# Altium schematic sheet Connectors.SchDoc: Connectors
size A3; Date: Not used; ApprovedBy: Not used; CheckedBy: Not used; Author: Not used; CompanyName: STMicroelectronics; DrawnBy: Not used; Engineer: Not used; Organization: Not used; Address1: Not used; Address2: Not used; Address3: Not used; Address4: Not used; DocumentNumber: 5; Revision: Not used; SheetNumber: 5; SheetTotal: 9
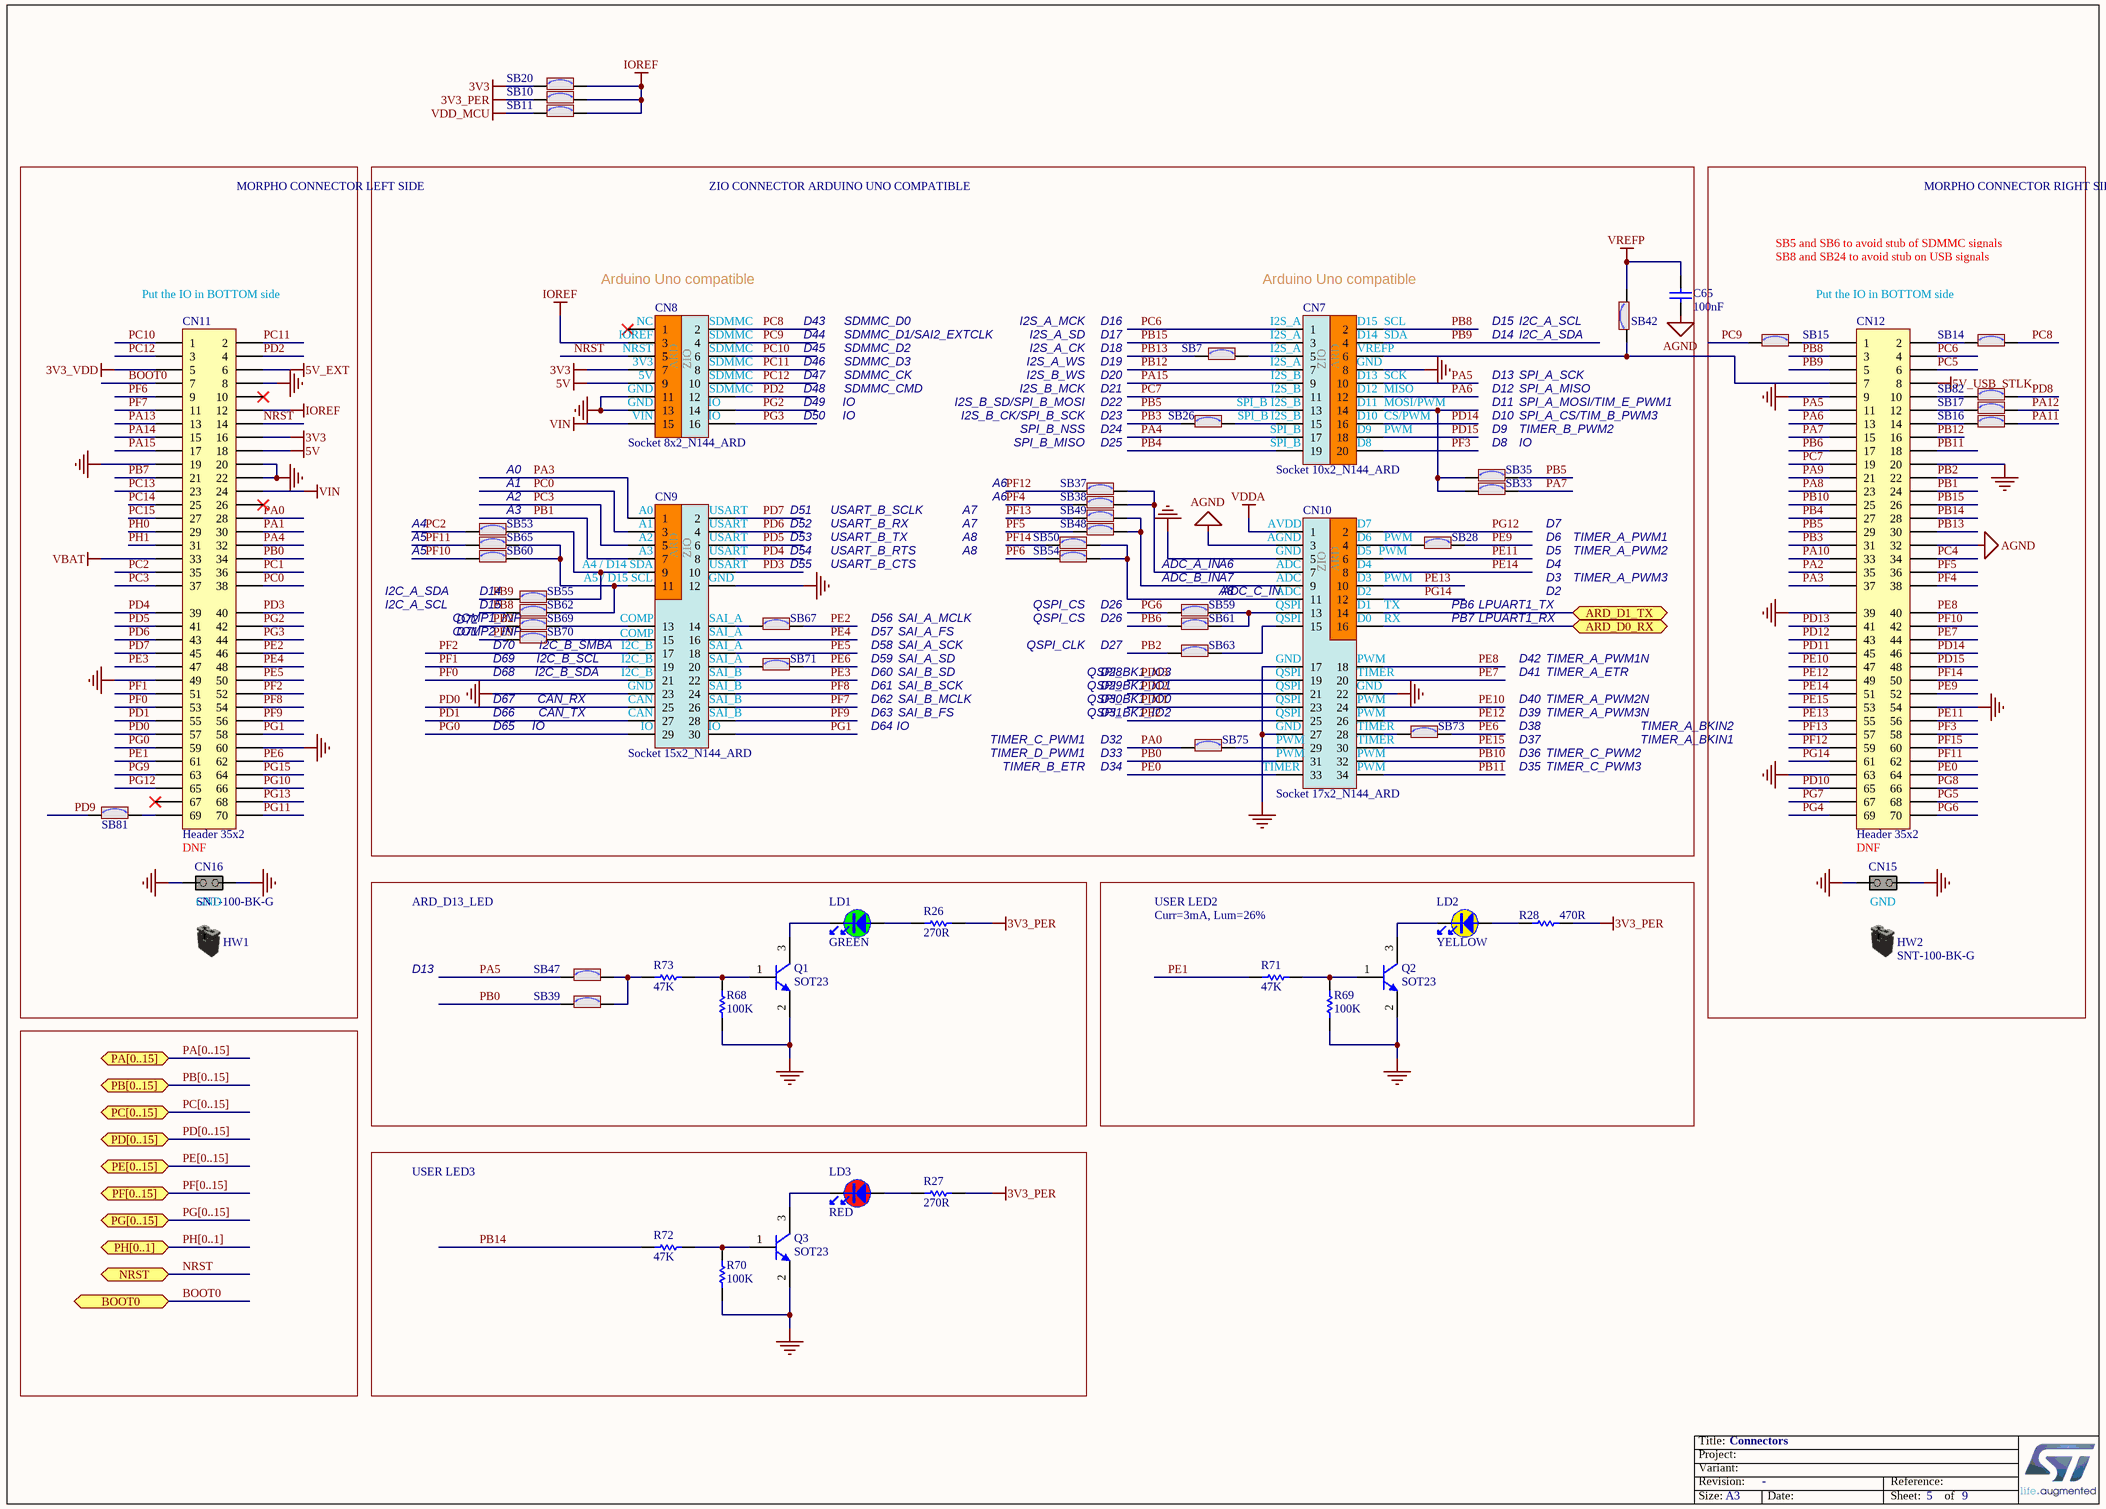
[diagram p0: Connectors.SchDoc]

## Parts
C65  value 100nF  [C0603]  (hidden comment: Capacitor)
CN7  Socket 10x2_N144_ARD  [CON_SAMTEC_SSW-110-23-X-D_N144_ARD]
CN8  Socket 8x2_N144_ARD  [CON_SAMTEC_SSW-108-23-X-D_N144_ARD]
CN9  Socket 15x2_N144_ARD  [CON_SAMTEC_SSW-115-23-X-D_N144_ARD]
CN10  Socket 17x2_N144_ARD  [CON_SAMTEC_SSW-117-23-X-D_N144_ARD]
CN11  Header 35x2  [CON_SAMTEC_TSW-135-07-X-D]
CN12  Header 35x2  [CON_SAMTEC_TSW-135-07-X-D]
CN15  Jumper_Header 2x1  [CON_SAMTEC_TSW-102-09-X-S]  (value not drawn)
CN16  Jumper_Header 2x1  [CON_SAMTEC_TSW-102-09-X-S]  (value not drawn)
HW1  value SNT-100-BK-G  (hidden comment: Shunt Black 2.54mm)  (mechanical)
HW2  value SNT-100-BK-G  (hidden comment: Shunt Black 2.54mm)  (mechanical)
LD1  value GREEN  [LED_0603_OSRAM_LG-Q396-PS-35_GREEN_1A2K_H0P4]  (hidden comment: LED_green)
LD2  value YELLOW  [LED_0603_OSRAM_LY-Q396-P1Q2-36_YELLOW_1A2K_H0P4]  (hidden comment: LED_yellow)
LD3  value RED  [LED_0603_OSRAM_LS-Q976-NR-1_RED_1A2K_H0P8]  (hidden comment: LED_red)
Q1  value SOT23  [NPN_SOT23]  (hidden comment: 9013-SOT23)
Q2  value SOT23  [NPN_SOT23]  (hidden comment: 9013-SOT23)
Q3  value SOT23  [NPN_SOT23]  (hidden comment: 9013-SOT23)
R26  value 270R  [R0402]  (hidden comment: Resistor)
R27  value 270R  [R0402]  (hidden comment: Resistor)
R28  value 470R  [R0402]  (hidden comment: Resistor)
R68  value 100K  [R0603]  (hidden comment: Resistor)
R69  value 100K  [R0603]  (hidden comment: Resistor)
R70  value 100K  [R0603]  (hidden comment: Resistor)
R71  value 47K  [R0603]  (hidden comment: Resistor)
R72  value 47K  [R0603]  (hidden comment: Resistor)
R73  value 47K  [R0603]  (hidden comment: Resistor)
SB7  SB_ON  [SOLDER-BRIDGE_R0603-0R]  (value not drawn)
SB10  SB_ON  [SOLDER-BRIDGE_R0603-0R]  (value not drawn)
SB11  SB_ON  [SOLDER-BRIDGE_R0603-0R]  (value not drawn)
SB14  SB_ON  [SOLDER-BRIDGE_R0603-0R]  (value not drawn)
SB15  SB_ON  [SOLDER-BRIDGE_R0603-0R]  (value not drawn)
SB16  SB_ON  [SOLDER-BRIDGE_R0603-0R]  (value not drawn)
SB17  SB_ON  [SOLDER-BRIDGE_R0603-0R]  (value not drawn)
SB20  SB_ON  [SOLDER-BRIDGE_R0603-0R]  (value not drawn)
SB26  SB_ON  [SOLDER-BRIDGE_R0603-0R]  (value not drawn)
SB28  SB_ON  [SOLDER-BRIDGE_R0402-0R]  (value not drawn)
SB33  SB_ON  [SOLDER-BRIDGE_R0603-0R]  (value not drawn)
SB35  SB_ON  [SOLDER-BRIDGE_R0603-0R]  (value not drawn)
SB37  SB_ON  [SOLDER-BRIDGE_R0402-0R]  (value not drawn)
SB38  SB_ON  [SOLDER-BRIDGE_R0402-0R]  (value not drawn)
SB39  SB_ON  [SOLDER-BRIDGE_R0603-0R]  (value not drawn)
SB42  SB_ON  [SOLDER-BRIDGE_R0603-0R]  (value not drawn)
SB47  SB_ON  [SOLDER-BRIDGE_R0603-0R]  (value not drawn)
SB48  SB_ON  [SOLDER-BRIDGE_R0402-0R]  (value not drawn)
SB49  SB_ON  [SOLDER-BRIDGE_R0402-0R]  (value not drawn)
SB50  SB_ON  [SOLDER-BRIDGE_R0402-0R]  (value not drawn)
SB53  SB_ON  [SOLDER-BRIDGE_R0402-0R]  (value not drawn)
SB54  SB_ON  [SOLDER-BRIDGE_R0402-0R]  (value not drawn)
SB55  SB_ON  [SOLDER-BRIDGE_R0402-0R]  (value not drawn)
SB59  SB_ON  [SOLDER-BRIDGE_R0402-0R]  (value not drawn)
SB60  SB_ON  [SOLDER-BRIDGE_R0402-0R]  (value not drawn)
SB61  SB_ON  [SOLDER-BRIDGE_R0402-0R]  (value not drawn)
SB62  SB_ON  [SOLDER-BRIDGE_R0402-0R]  (value not drawn)
SB63  SB_ON  [SOLDER-BRIDGE_R0402-0R]  (value not drawn)
SB65  SB_ON  [SOLDER-BRIDGE_R0402-0R]  (value not drawn)
SB67  SB_ON  [SOLDER-BRIDGE_R0402-0R]  (value not drawn)
SB69  SB_ON  [SOLDER-BRIDGE_R0402-0R]  (value not drawn)
SB70  SB_ON  [SOLDER-BRIDGE_R0402-0R]  (value not drawn)
SB71  SB_ON  [SOLDER-BRIDGE_R0402-0R]  (value not drawn)
SB73  SB_ON  [SOLDER-BRIDGE_R0402-0R]  (value not drawn)
SB75  SB_ON  [SOLDER-BRIDGE_R0402-0R]  (value not drawn)
SB81  SB_ON  [SOLDER-BRIDGE_R0402-0R]  (value not drawn)
SB82  SB_ON  [SOLDER-BRIDGE_R0402-0R]  (value not drawn)

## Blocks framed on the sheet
USER LED3: LD3 Q3 R27 R70 R72

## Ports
ARD_D0_RX (bidir), ARD_D1_TX (bidir), BOOT0, NRST, PA[0..15] (bidir), PB[0..15] (bidir), PC[0..15] (bidir), PD[0..15] (bidir), PE[0..15] (bidir), PF[0..15] (bidir), PG[0..15] (bidir), PH[0..1] (bidir)

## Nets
3V3: CN8.7 CN11.16 SB20.1
3V3_PER: R26.2 R27.2 R28.2 SB10.1
3V3_VDD: CN11.5
5V: CN8.9 CN11.18
5V_EXT: CN11.6
5V_USB_STLK: CN12.8
AGND: C65.1 CN10.3 CN12.32
GND: CN7.8 CN8.11 CN8.13 CN9.12 CN9.23 CN10.5 CN10.17 CN10.22 CN10.27 CN11.8 CN11.19 CN11.20 CN11.22 CN11.49 CN11.60 CN12.9 CN12.20 CN12.39 CN12.54 CN12.63 CN15.1(COMMON) CN15.2(NO) CN16.1(COMMON) CN16.2(NO) Q1.2(E) Q2.2(E) Q3.2(E) R68.1 R69.1 R70.1
IOREF: CN8.3 CN11.12 SB10.2 SB11.2 SB20.2
VBAT: CN11.33
VDD_MCU: SB11.1
VDDA: CN10.1
VIN: CN8.15 CN11.24
VREFP: C65.2 SB42.2
ARD_D0_RX: CN10.16 ; port ARD_D0_RX
ARD_D1_TX: CN10.14 ; port ARD_D1_TX
BOOT0: CN11.7 ; port BOOT0
NRST: CN8.5 CN11.14 ; port NRST
PA0: CN11.28 SB75.1
PA1: CN11.30
PA2: CN12.35
PA3: CN9.1 CN12.37
PA4: CN7.17 CN11.32
PA5: CN7.10 CN12.11 SB47.1
PA6: CN7.12 CN12.13
PA7: CN12.15 SB33.2
PA8: CN12.23
PA9: CN12.21
PA10: CN12.33
PA11: SB16.2
PA12: SB17.2
PA13: CN11.13
PA14: CN11.15
PA15: CN7.9 CN11.17
PB0: CN10.31 CN11.34 SB39.1
PB1: CN9.7 CN12.24
PB2: CN12.22 SB63.1 SB69.1
PB3: CN12.31 SB26.1
PB4: CN7.19 CN12.27
PB5: CN7.13 CN12.29 SB35.2
PB6: CN12.17 SB61.1
PB7: CN11.21
PB8: CN7.2 CN12.3 SB62.1
PB9: CN7.4 CN12.5 SB55.1
PB10: CN10.32 CN12.25
PB11: CN10.34 CN12.18
PB12: CN7.7 CN12.16
PB13: CN12.30 SB7.1
PB14: CN12.28 R72.1
PB15: CN7.3 CN12.26
PC0: CN9.3 CN11.38
PC1: CN11.36
PC2: CN11.35 SB53.1
PC3: CN9.5 CN11.37
PC4: CN12.34
PC5: CN12.6
PC6: CN7.1 CN12.4
PC7: CN7.11 CN12.19
PC8: CN8.2 SB14.2
PC9: CN8.4 SB15.1
PC10: CN8.6 CN11.1
PC11: CN8.8 CN11.2
PC12: CN8.10 CN11.3
PC13: CN11.23
PC14: CN11.25
PC15: CN11.27
PD0: CN9.25 CN11.57
PD1: CN9.27 CN11.55
PD2: CN8.12 CN11.4
PD3: CN9.10 CN11.40
PD4: CN9.8 CN11.39
PD5: CN9.6 CN11.41
PD6: CN9.4 CN11.43
PD7: CN9.2 CN11.45
PD8: SB82.2
PD9: SB81.1
PD10: CN12.65
PD11: CN10.23 CN12.45
PD12: CN10.21 CN12.43
PD13: CN10.19 CN12.41
PD14: CN7.16 CN12.46
PD15: CN7.18 CN12.48
PE0: CN10.33 CN12.64
PE1: CN11.61 R71.1
PE2: CN10.25 CN11.46 SB67.2
PE3: CN9.22 CN11.47
PE4: CN9.16 CN11.48
PE5: CN9.18 CN11.50
PE6: CN11.62 SB71.2 SB73.2
PE7: CN10.20 CN12.44
PE8: CN10.18 CN12.40
PE9: CN12.52 SB28.2 SB70.1
PE10: CN10.24 CN12.47
PE11: CN10.6 CN12.56
PE12: CN10.26 CN12.49
PE13: CN10.10 CN12.55
PE14: CN10.8 CN12.51
PE15: CN10.30 CN12.53
PF0: CN9.21 CN11.53
PF1: CN9.19 CN11.51
PF2: CN9.17 CN11.52
PF3: CN7.20 CN12.58
PF4: CN12.38 SB38.1
PF5: CN12.36 SB48.1
PF6: CN11.9 SB54.1
PF7: CN9.26 CN11.11
PF8: CN9.24 CN11.54
PF9: CN9.28 CN11.56
PF10: CN12.42 SB60.1
PF11: CN12.62 SB65.1
PF12: CN12.59 SB37.1
PF13: CN12.57 SB49.1
PF14: CN12.50 SB50.1
PF15: CN12.60
PG0: CN9.29 CN11.59
PG1: CN9.30 CN11.58
PG2: CN8.14 CN11.42
PG3: CN8.16 CN11.44
PG4: CN12.69
PG5: CN12.68
PG6: CN12.70 SB59.1
PG7: CN12.67
PG8: CN12.66
PG9: CN11.63
PG10: CN11.66
PG11: CN11.70
PG12: CN10.2 CN11.65
PG13: CN11.68
PG14: CN10.12 CN12.61
PG15: CN11.64
PH0: CN11.29
PH1: CN11.31
NetCN7_5: CN7.5 SB7.2
NetCN7_6: CN7.6 CN12.7 SB42.1
NetCN7_14: CN7.14 SB33.1 SB35.1
NetCN7_15: CN7.15 SB26.2
NetCN9_9: CN9.9 SB53.2 SB55.2
NetCN9_11: CN9.11 SB60.2 SB62.2 SB65.2
NetCN9_13: CN9.13 SB69.2
NetCN9_14: CN9.14 SB67.1
NetCN9_15: CN9.15 SB70.2
NetCN9_20: CN9.20 SB71.1
NetCN10_4: CN10.4 SB28.1
NetCN10_7: CN10.7 SB37.2 SB38.2
NetCN10_9: CN10.9 SB48.2 SB49.2
NetCN10_11: CN10.11 SB50.2 SB54.2
NetCN10_13: CN10.13 SB59.2 SB61.2
NetCN10_15: CN10.15 SB63.2
NetCN10_28: CN10.28 SB73.1
NetCN10_29: CN10.29 SB75.2
NetCN11_69: CN11.69 SB81.2
NetCN12_1: CN12.1 SB15.2
NetCN12_2: CN12.2 SB14.1
NetCN12_10: CN12.10 SB82.1
NetCN12_12: CN12.12 SB17.1
NetCN12_14: CN12.14 SB16.1
NetLD1_1: LD1.1 R26.1
NetLD1_2: LD1.2 Q1.3(C)
NetLD2_1: LD2.1 R28.1
NetLD2_2: LD2.2 Q2.3(C)
NetLD3_1: LD3.1 R27.1
NetLD3_2: LD3.2 Q3.3(C)
NetQ1_1: Q1.1(B) R68.2 R73.2
NetQ2_1: Q2.1(B) R69.2 R71.2
NetQ3_1: Q3.1(B) R70.2 R72.2
NetR73_1: R73.1 SB39.2 SB47.2

Not connected (* = marked no-connect by the designer): CN8 1*; CN11 10* 26* 67*

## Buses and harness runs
bus PA[0..15] = port PA[0..15]
bus PB[0..15] = port PB[0..15]
bus PC[0..15] = port PC[0..15]
bus PD[0..15] = port PD[0..15]
bus PE[0..15] = port PE[0..15]
bus PF[0..15] = port PF[0..15]
bus PG[0..15] = port PG[0..15]
bus PH[0..1] = port PH[0..1]

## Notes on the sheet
- MORPHO CONNECTOR LEFT SIDE
- ZIO CONNECTOR ARDUINO UNO COMPATIBLE
- MORPHO CONNECTOR RIGHT SIDE
- (near CN11) Put the IO in BOTTOM side
- (near CN8) Arduino Uno compatible
- (near CN7) Arduino Uno compatible
- SB5 and SB6 to avoid stub of SDMMC signals
- SB8 and SB24 to avoid stub on USB signals
- Put the IO in BOTTOM side
- (near CN8) NC
- (near CN8) IOREF
- (near CN8) NRST
- (near CN8) 3V3
- (near CN8) 5V
- (near CN8) SDMMC
- D43
- D44
- D45
- D46
- D47
- SDMMC_CK
- SDMMC_D0
- SDMMC_D1/SAI2_EXTCLK
- SDMMC_D2
- SDMMC_D3
- I2S_A_SD
- I2S_A_CK
- I2S_A_WS
- I2S_A_MCK
- I2S_B_WS
- D16
- D17
- D18
- D19
- D20
- (near CN7) I2S_A
- (near CN7) I2S_B
- (near CN7) VREFP
- (near CN7) D13
- (near CN7) D14
- (near CN7) D15
- (near CN7) SCL
- (near CN7) SDA
- (near CN7) SCK
- (near CN7) GND
- D15
- D14
- D13
- SPI_A_SCK
- (near SB42) I2C_A_SCL
- (near SB42) I2C_A_SDA
- (near CN8) GND
- (near CN8) VIN
- (near CN8) IO
- D48
- D49
- D50
- SDMMC_CMD
- IO
- I2S_B_SD/SPI_B_MOSI
- I2S_B_CK/SPI_B_SCK
- I2S_B_MCK
- SPI_B_MISO
- SPI_B_NSS
- D21
- D22
- D23
- D24
- D25
- SPI_B
- (near SB26) SPI_B
- (near CN7) SPI_B
- (near CN7) D8
- (near CN7) D9
- (near CN7) D10
- (near CN7) D11
- (near CN7) D12
- (near CN7) MISO
- (near CN7) MOSI/PWM
- (near CN7) CS/PWM
- (near CN7) PWM
- D12
- D11
- D10
- D9
- D8
- TIMER_B_PWM2
- SPI_A_CS/TIM_B_PWM3
- SPI_A_MOSI/TIM_E_PWM1
- SPI_A_MISO
- A0
- A1
- A2
- (near SB53) A3
- (near CN9) A0
- (near CN9) USART
- D51
- USART_B_SCLK
- A7
- A6
- A4
- A5
- (near CN9) A1
- (near CN9) A2
- (near CN9) A3
- (near CN9) A4 / D14 SDA
- (near CN9) A5 / D15 SCL
- (near CN9) GND
- D52
- D53
- D54
- D55
- USART_B_TX
- USART_B_RX
- USART_B_CTS
- USART_B_RTS
- A8
- ADC_A_IN
- ADC_B_IN
- (near CN10) GND
- (near CN10) AVDD
- (near CN10) AGND
- (near CN10) ADC
- (near CN10) D7
- (near CN10) D6
- (near CN10) D5
- (near CN10) D4
- (near CN10) D3
- PWM
- D5
- D6
- D7
- D4
- D3
- TIMER_A_PWM1
- TIMER_A_PWM2
- TIMER_A_PWM3
- I2C_A_SCL
- I2C_A_SDA
- COMP1_INP
- COMP2_INP
- D72
- D71
- D70
- (near SB70) I2C_B_SMBA
- (near CN9) COMP
- (near CN9) I2C_B
- (near CN9) SAI_A
- D56
- D57
- D58
- SAI_A_SCK
- SAI_A_FS
- SAI_A_MCLK
- QSPI_CLK
- QSPI_CS
- D26
- D27
- (near SB59) ADC_C_IN
- (near CN10) QSPI
- (near CN10) D2
- (near CN10) D1
- (near CN10) D0
- (near CN10) TX
- (near CN10) RX
- PB6
- PB7
- LPUART1_TX
- LPUART1_RX
- D2
- (near SB70) D69
- D68
- D67
- D66
- CAN_TX
- CAN_RX
- (near SB70) I2C_B_SCL
- I2C_B_SDA
- (near CN9) CAN
- (near CN9) SAI_B
- D59
- D60
- D61
- D62
- D63
- SAI_A_SD
- SAI_B_SD
- SAI_B_SCK
- SAI_B_FS
- SAI_B_MCLK
- QSPI_BK1_IO0
- QSPI_BK1_IO2
- QSPI_BK1_IO1
- QSPI_BK1_IO3
- D28
- D29
- D30
- D31
- (near CN10) TIMER
- (near CN10) PWM
- D39
- D40
- D41
- D42
- TIMER_A_PWM1N
- TIMER_A_PWM2N
- TIMER_A_PWM3N
- TIMER_A_ETR
- D65
- (near CN9) IO
- D64
- TIMER_D_PWM1
- TIMER_B_ETR
- TIMER_C_PWM1
- D32
- D33
- D34
- D35
- D36
- D37
- D38
- TIMER_C_PWM2
- TIMER_C_PWM3
- TIMER_A_BKIN1
- TIMER_A_BKIN2
- DNF
- GND
- ARD_D13_LED
- USER LED2
- Curr=3mA, Lum=26%

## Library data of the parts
C65 = MCD-00237: Capacitor, MLCC, 100nF, 6V3, X5R, 10%, 0603, T=0,8mm; Manufacturer_Part_Number: CC0603KRX5R5BB104; Manufacturer: YAGEO; Provided_By: SUBCO; ECCN_US: EAR99; ECCN_EU: NEC
CN7 = MCD-01039: Socket, 10x2, 2.54mm, VR, TH, Height 8.51mm/10mm, Low insertion force.; Part_Type: Connector; Manufacturer_Part_Number: SSW-110-23-x-D; Manufacturer: SAMTEC; Provided_By: SUBCO
CN8 = MCD-01037: Socket, 8x2, 2.54mm, VR, TH, Height 8.51mm/10mm, Low insertion force.; Part_Type: Connector; Manufacturer_Part_Number: SSW-108-23-x-D; Manufacturer: SAMTEC; Provided_By: SUBCO
CN9 = MCD-01040: Socket, 15x2, 2.54mm, VR, TH, Height 8.51mm/10mm, Low insertion force.; Part_Type: Connector; Manufacturer_Part_Number: SSW-115-23-x-D; Manufacturer: SAMTEC; Provided_By: SUBCO
CN10 = MCD-01041: Socket, 17x2, 2.54mm, VR, TH, Height 8.51mm/10mm, Low insertion force; Part_Type: Connector; Manufacturer_Part_Number: SSW-117-23-x-D; Manufacturer: SAMTEC; Provided_By: SUBCO
CN11 CN12 = MCD-01210: Header, 35x2, 2,54mm, VR, TH, Height 5.84mm/2.54mm; Part_Type: Connector; Manufacturer_Part_Number: TSW-135-07-x-D; Manufacturer: SAMTEC; Provided_By: SUBCO
CN15 CN16 = MCD-00214: Header, 2x1, 2,54mm, VR, TH, Height 5.84mm/10.16mm; Manufacturer_Part_Number: TSW-102-09-x-S; Manufacturer: SAMTEC; Part_Type: Connector; Value: Header 2x1 16mm; Provided_By: SUBCO
HW1 HW2 = MCD-00043: SHUNT 2.54mm BLACK; Manufacturer: SAMTEC; Part_Type: Mechanical; Alternate_Manufacturer_Part_Number: 316102S111A; Alternate_Manufacturer: JIUBABA; Provided_By: SUBCO
LD1 = MCD-00588: LED Green, 0603 SMD, Forward Voltage Typ=2V, Max=2.5V; Part_Type: Display; Manufacturer_Part_Number: LG Q396-PS-35; Manufacturer: OSRAM OPTO SEMICONDUCTORS; Alternate_Manufacturer_Part_Number: VLMTG1300-GS08; Alternate_Manufacturer: VISHAY SEMICONDUCTOR OPTO DIVISION; Provided_By: SUBCO
LD2 = MCD-01061: LED Yellow, 0603 SMD, Forward Voltage min=1.7V, Typ=2V, Max=2.3V; Part_Type: Display; Manufacturer_Part_Number: LY Q396-P1Q2-36; Manufacturer: OSRAM OPTO SEMICONDUCTORS; Provided_By: SUBCO
LD3 = MCD-00586: LED Red, 0603 SMD, Forward Voltage Typ=2V, Max=2.5V; Part_Type: Display; Manufacturer_Part_Number: LS Q976-NR-1; Manufacturer: OSRAM OPTO SEMICONDUCTORS; Alternate_Manufacturer_Part_Number: VLMS1300-GS08; Alternate_Manufacturer: VISHAY SEMICONDUCTOR OPTO DIVISION; Provided_By: SUBCO
Q1-Q3 = MCD-00073: NPN Bipolar Transistor; Part_Type: IC; Manufacturer_Part_Number: BSR14; Manufacturer: ON SEMICONDUCTOR; Alternate_Manufacturer_Part_Number: MMBT2222ALT1G / MMBT2222ALT3G; Provided_By: SUBCO; ECCN_US: EAR99; ECCN_EU: NEC
R26 R27 = MCD-00441: Resistor,270R,0402,1%,1/16W; Manufacturer_Part_Number: RC0402FR-07270RL; Manufacturer: YAGEO; Provided_By: SUBCO; ECCN_US: EAR99; ECCN_EU: NEC
R28 = MCD-00178: Resistor,470R,0402,1%,1/16W; Manufacturer_Part_Number: RC0402FR-07470RL; Manufacturer: YAGEO; Provided_By: SUBCO; ECCN_US: EAR99; ECCN_EU: NEC
R68-R70 = MCD-00223: Resistor,100K,0603,1%,1/10W; Manufacturer_Part_Number: RC0603FR-07100KL; Manufacturer: YAGEO; Provided_By: SUBCO; ECCN_US: EAR99; ECCN_EU: NEC
R71-R73 = MCD-00222: Resistor,47K,0603,1%,1/10W; Manufacturer_Part_Number: RC0603FR-0747KL; Manufacturer: YAGEO; Provided_By: SUBCO; ECCN_US: EAR99; ECCN_EU: NEC
SB7 SB10 SB11 SB14-SB17 SB20 SB26 SB33 SB35 SB39 SB42 SB47 = MCD-00071: Solder Bridge ON; Part_Type: Mechanical; Manufacturer_Part_Number: RC0603JR-070RL; Manufacturer: YAGEO; Provided_By: SUBCO
SB28 SB37 SB38 SB48-SB50 SB53-SB55 SB59-SB63 SB65 SB67 SB69-SB71 SB73 SB75 SB81 SB82 = MCD-01618: Solder Bridge 0402 ON; Part_Type: Mechanical; Manufacturer_Part_Number: RC0402JR-070RL; Manufacturer: YAGEO; Provided_By: SUBCO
